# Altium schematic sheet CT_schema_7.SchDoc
size 255 x 245 mm
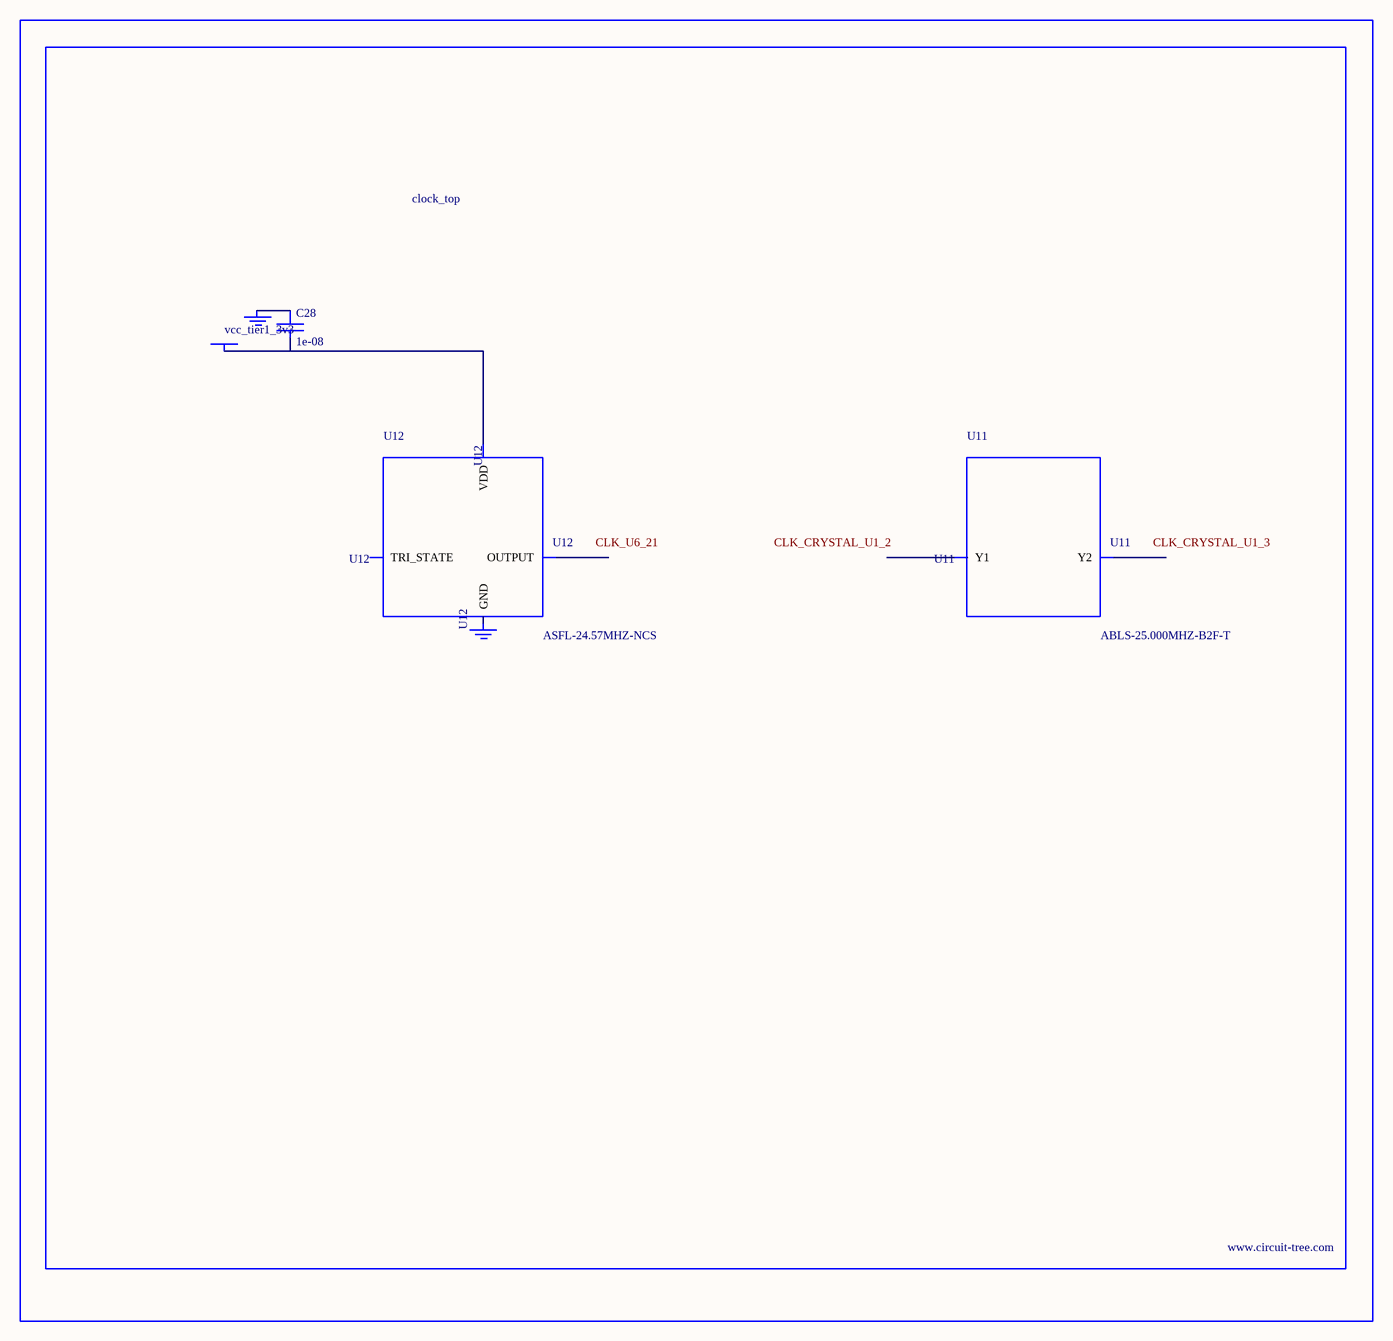
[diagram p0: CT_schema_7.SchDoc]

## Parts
BORDER6  (no value)
C28  1e-08  [C0402]
GND_INSTANCE_6_0  (no value)
GND_INSTANCE_6_1  (no value)
POWER_INSTANCE_6_0  vcc_tier1_3v3
U11  ABLS-25.000MHZ-B2F-T  [ABLS-25.000MHZ-B2F-T]
U12  ASFL-24.57MHZ-NCS  [ASFL1]

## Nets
NetC28_1: C28.1 GND_INSTANCE_6_0.0(GND)
NetC28_2: C28.2 POWER_INSTANCE_6_0.0(PWR) U12.4(VDD)

Not connected (* = marked no-connect by the designer): GND_INSTANCE_6_1 0(GND); U11 1(Y1) 2(Y2); U12 1(TRI_STATE) 2(GND) 3(OUTPUT)

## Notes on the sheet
- Labels drawn without touching a wire or pin: CLK_CRYSTAL_U1_2, CLK_CRYSTAL_U1_3, CLK_U6_21

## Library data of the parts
BORDER6 = BORDER_PAGE6
C28 = C0402C103K3RAC
GND_INSTANCE_6_0 GND_INSTANCE_6_1 = GND
POWER_INSTANCE_6_0 = PWR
